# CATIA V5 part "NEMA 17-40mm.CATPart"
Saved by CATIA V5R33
Part number: NEMA 17-40mm
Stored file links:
  C:\Users\Ryzen5700u\Desktop\robot_cicloidale_singolo\Assieme_robot_cicloidale_singolo\NEMA 17-40mm.CATPart

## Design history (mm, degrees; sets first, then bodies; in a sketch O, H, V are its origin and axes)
Body1 "Solido1" (main body)
  Solid1: solid without history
